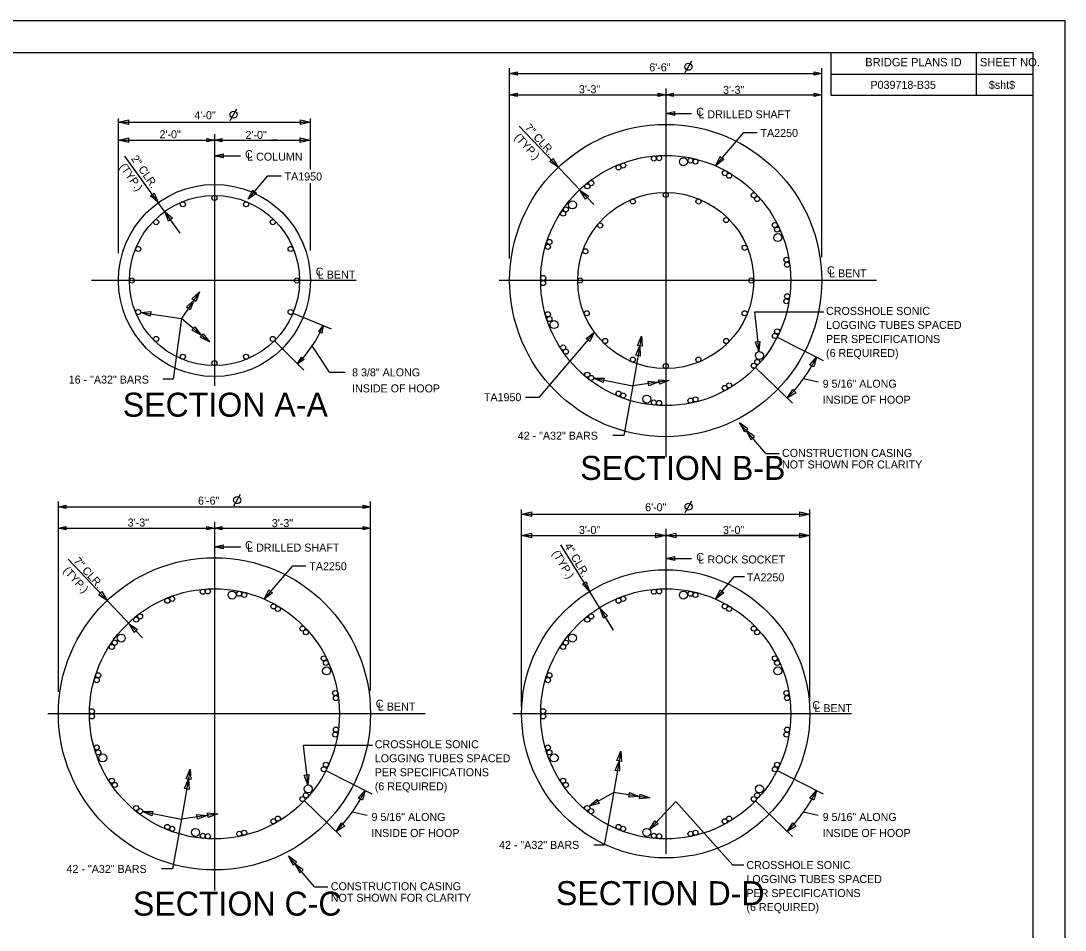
# Model space of a CAD drawing. Extents: x -225.1 to -152.9, y -16.8 to 27.2.
# Drawn here: x -185.7 to -153.08, y -1.16 to 27.22 of the extents above; entities that cross this region are included whole.
import ezdxf

# ---------------------------------------------------------------- set-up
doc = ezdxf.new("R2010")
doc.units = 0
for name, color, linetype in [('BR_AUTO DIMENSION', 7, 'Continuous'), ('BR_BORDER LINES', 7, 'Continuous'), ('BR_CENTER LINES', 7, 'Continuous'), ('BR_CONCRETE', 7, 'Continuous'), ('BR_REBAR', 7, 'Continuous'), ('BR_TEXT', 7, 'Continuous'), ('Level 31', 7, 'Continuous')]:
    doc.layers.add(name, color=color, linetype=linetype)

msp = doc.modelspace()

# ---------------------------------------------------------------- linework, layer by layer
at = {"layer": 'BR_AUTO DIMENSION'}
for p, q in [((-170.43, 19.805), (-170.43, 25.748)), ((-170.43, 25.58), (-160.68, 25.58)), ((-160.68, 19.843), (-160.68, 25.748)), ((-170.43, 24.914), (-165.555, 24.914)), ((-165.555, 24.914), (-160.68, 24.914)), ((-182.652, 19.974), (-182.652, 24.175)), ((-176.652, 22.581), (-176.652, 24.175)), ((-165.555, 24.335), (-164.744, 24.335)), ((-182.652, 24.066), (-176.652, 24.066)), ((-167.801, 21.487), (-170.129, 23.942)), ((-182.652, 23.503), (-176.652, 23.503)), ((-164.001, 22.702), (-163.111, 23.742)), ((-163.111, 23.742), (-162.698, 23.742)), ((-180.722, 20.6), (-182.453, 22.996)), ((-179.652, 23.013), (-178.841, 23.013)), ((-178.6, 21.659), (-177.98, 22.383)), ((-177.98, 22.383), (-177.567, 22.383)), ((-176.652, 20.054), (-176.652, 22.159)), ((-180.118, 18.763), (-180.684, 17.937)), ((-181.954, 18.12), (-180.684, 17.937)), ((-177.198, 18.102), (-176.002, 17.606)), ((-160.615, 18.132), (-162.786, 18.132)), ((-162.786, 18.132), (-162.643, 16.9)), ((-180.684, 17.937), (-180.942, 16.04)), ((-179.809, 17.197), (-180.684, 17.937)), ((-167.78, 17.501), (-169.523, 15.462)), ((-166.312, 17.386), (-166.584, 15.828)), ((-162.072, 17.351), (-160.639, 16.624)), ((-177.774, 17.24), (-176.858, 16.324)), ((-176.061, 16.256), (-176.597, 17.077)), ((-162.748, 16.402), (-161.593, 15.285)), ((-180.942, 16.04), (-181.262, 16.04)), ((-176.061, 16.256), (-175.564, 16.256)), ((-167.8, 16.069), (-166.584, 15.828)), ((-165.451, 15.997), (-166.584, 15.828)), ((-160.789, 15.946), (-161.252, 16.052)), ((-166.584, 15.828), (-166.862, 14.277)), ((-169.523, 15.462), (-169.936, 15.462)), ((-162.427, 13.719), (-163.245, 14.674)), ((-166.862, 14.277), (-167.211, 14.277)), ((-162.427, 13.719), (-162.014, 13.719)), ((-184.527, 6.277), (-184.527, 12.22)), ((-174.777, 6.315), (-174.777, 12.22)), ((-184.527, 12.052), (-174.777, 12.052)), ((-170.055, 5.815), (-170.055, 11.971)), ((-170.055, 11.825), (-161.055, 11.825)), ((-161.055, 5.995), (-161.055, 11.971)), ((-184.527, 11.386), (-179.652, 11.386)), ((-179.652, 11.386), (-174.777, 11.386)), ((-170.055, 11.158), (-165.555, 11.158)), ((-165.555, 11.158), (-161.055, 11.158)), ((-179.652, 10.807), (-178.841, 10.807)), ((-167.182, 8.204), (-168.835, 10.861)), ((-181.898, 7.959), (-184.226, 10.414)), ((-178.097, 9.174), (-177.207, 10.214)), ((-177.207, 10.214), (-176.795, 10.214)), ((-165.555, 10.436), (-164.744, 10.436)), ((-164.001, 9.174), (-163.402, 9.875)), ((-163.402, 9.875), (-163.092, 9.875)), ((-174.712, 4.604), (-176.882, 4.604)), ((-176.882, 4.604), (-176.74, 3.372)), ((-166.958, 4.424), (-167.23, 2.865)), ((-180.408, 3.858), (-180.681, 2.3)), ((-176.168, 3.823), (-174.735, 3.096)), ((-162.072, 3.823), (-160.639, 3.096)), ((-167.947, 2.704), (-167.182, 3.138)), ((-166.05, 2.961), (-167.182, 3.138)), ((-176.844, 2.875), (-175.689, 1.757)), ((-167.23, 2.865), (-167.476, 1.492)), ((-165.234, 2.851), (-166.057, 1.974)), ((-163.454, 0.862), (-165.234, 2.851)), ((-162.748, 2.875), (-161.593, 1.757)), ((-181.896, 2.541), (-180.681, 2.3)), ((-180.681, 2.3), (-180.959, 0.749)), ((-179.547, 2.469), (-180.681, 2.3)), ((-174.885, 2.418), (-175.349, 2.524)), ((-160.789, 2.418), (-161.252, 2.524)), ((-167.476, 1.492), (-167.796, 1.492)), ((-176.524, 0.191), (-177.341, 1.147)), ((-180.959, 0.749), (-181.308, 0.749)), ((-163.113, 0.862), (-163.454, 0.862)), ((-176.524, 0.191), (-176.111, 0.191))]:
    msp.add_line(p, q, dxfattribs=at)
for points in [[(-170.196, 25.526), (-170.43, 25.58), (-170.196, 25.634)], [(-160.914, 25.634), (-160.68, 25.58), (-160.914, 25.526)], [(-170.196, 24.86), (-170.43, 24.914), (-170.196, 24.968)], [(-165.789, 24.968), (-165.555, 24.914), (-165.789, 24.86)], [(-165.321, 24.86), (-165.555, 24.914), (-165.321, 24.968)], [(-160.914, 24.968), (-160.68, 24.914), (-160.914, 24.86)], [(-165.278, 24.271), (-165.555, 24.335), (-165.278, 24.399)], [(-182.34, 23.994), (-182.652, 24.066), (-182.34, 24.138)], [(-176.964, 24.138), (-176.652, 24.066), (-176.964, 23.994)], [(-182.34, 23.431), (-182.652, 23.503), (-182.34, 23.575)], [(-179.886, 23.557), (-179.652, 23.503), (-179.886, 23.449)], [(-179.418, 23.449), (-179.652, 23.503), (-179.418, 23.557)], [(-176.973, 23.573), (-176.661, 23.501), (-176.973, 23.429)], [(-179.375, 22.949), (-179.652, 23.013), (-179.375, 23.077)], [(-169.072, 22.932), (-168.91, 22.656), (-169.177, 22.832)], [(-163.743, 22.892), (-164.001, 22.702), (-163.853, 22.986)], [(-178.342, 21.849), (-178.6, 21.659), (-178.451, 21.943)], [(-168.059, 21.654), (-168.222, 21.93), (-167.955, 21.753)], [(-181.533, 21.845), (-181.409, 21.55), (-181.65, 21.761)], [(-181.083, 20.976), (-181.207, 21.271), (-180.966, 21.061)], [(-180.354, 18.547), (-180.118, 18.764), (-180.235, 18.465)], [(-180.53, 18.289), (-180.295, 18.506), (-180.411, 18.208)], [(-181.656, 18.004), (-181.954, 18.12), (-181.635, 18.147)], [(-180.261, 17.673), (-180.069, 17.417), (-180.354, 17.563)], [(-176.394, 17.515), (-176.257, 17.712), (-176.294, 17.475)], [(-180.003, 17.456), (-179.811, 17.199), (-180.096, 17.346)], [(-168.037, 17.311), (-167.78, 17.501), (-167.928, 17.217)], [(-166.437, 17.091), (-166.312, 17.386), (-166.295, 17.066)], [(-166.49, 16.784), (-166.366, 17.079), (-166.348, 16.759)], [(-162.61, 17.218), (-162.643, 16.9), (-162.753, 17.201)], [(-176.854, 16.654), (-177.054, 16.52), (-176.933, 16.728)], [(-161.056, 16.488), (-160.843, 16.727), (-160.929, 16.419)], [(-167.511, 15.93), (-167.8, 16.069), (-167.48, 16.071)], [(-165.772, 16.022), (-165.453, 15.997), (-165.751, 15.879)], [(-166.106, 15.971), (-165.787, 15.946), (-166.085, 15.829)], [(-161.484, 15.611), (-161.757, 15.444), (-161.584, 15.714)], [(-162.987, 14.484), (-163.245, 14.674), (-163.097, 14.39)], [(-162.784, 14.247), (-163.042, 14.437), (-162.894, 14.153)], [(-184.293, 11.998), (-184.527, 12.052), (-184.293, 12.106)], [(-175.011, 12.106), (-174.777, 12.052), (-175.011, 11.998)], [(-169.743, 11.753), (-170.055, 11.825), (-169.743, 11.897)], [(-161.367, 11.897), (-161.055, 11.825), (-161.367, 11.753)], [(-184.293, 11.332), (-184.527, 11.386), (-184.293, 11.44)], [(-179.886, 11.44), (-179.652, 11.386), (-179.886, 11.332)], [(-179.418, 11.332), (-179.652, 11.386), (-179.418, 11.44)], [(-175.011, 11.44), (-174.777, 11.386), (-175.011, 11.332)], [(-169.743, 11.086), (-170.055, 11.158), (-169.743, 11.23)], [(-165.867, 11.23), (-165.555, 11.158), (-165.867, 11.086)], [(-165.243, 11.086), (-165.555, 11.158), (-165.243, 11.23)], [(-161.367, 11.23), (-161.055, 11.158), (-161.367, 11.086)], [(-179.375, 10.743), (-179.652, 10.807), (-179.375, 10.871)], [(-165.278, 10.372), (-165.555, 10.436), (-165.278, 10.5)], [(-168.037, 9.714), (-167.933, 9.411), (-168.159, 9.638)], [(-183.169, 9.404), (-183.006, 9.128), (-183.273, 9.305)], [(-177.84, 9.364), (-178.097, 9.174), (-177.949, 9.458)], [(-163.744, 9.364), (-164.001, 9.174), (-163.853, 9.458)], [(-167.499, 8.577), (-167.603, 8.88), (-167.377, 8.654)], [(-182.156, 8.126), (-182.318, 8.402), (-182.051, 8.225)], [(-167.082, 4.129), (-166.958, 4.423), (-166.941, 4.104)], [(-167.136, 3.821), (-167.011, 4.116), (-166.994, 3.796)], [(-180.533, 3.563), (-180.408, 3.858), (-180.391, 3.538)], [(-176.707, 3.691), (-176.74, 3.372), (-176.85, 3.673)], [(-180.587, 3.256), (-180.462, 3.551), (-180.445, 3.231)], [(-175.152, 2.96), (-174.94, 3.199), (-175.026, 2.891)], [(-166.684, 3.132), (-166.386, 3.013), (-166.706, 2.99)], [(-166.35, 3.081), (-166.053, 2.962), (-166.372, 2.939)], [(-161.056, 2.96), (-160.843, 3.199), (-160.929, 2.891)], [(-167.638, 2.788), (-167.947, 2.704), (-167.705, 2.915)], [(-181.608, 2.402), (-181.896, 2.541), (-181.576, 2.543)], [(-180.203, 2.443), (-179.884, 2.418), (-180.181, 2.301)], [(-179.869, 2.494), (-179.55, 2.469), (-179.848, 2.352)], [(-175.58, 2.083), (-175.854, 1.917), (-175.681, 2.186)], [(-165.79, 2.152), (-166.057, 1.974), (-165.895, 2.251)], [(-161.484, 2.083), (-161.757, 1.917), (-161.584, 2.186)], [(-177.084, 0.956), (-177.341, 1.147), (-177.193, 0.863)], [(-176.881, 0.719), (-177.138, 0.909), (-176.99, 0.626)]]:
    msp.add_lwpolyline(points, close=True, dxfattribs=at)
for centre in [(-165.003, 22.827), (-168.467, 21.481), (-162.053, 20.458), (-169.043, 17.741), (-162.627, 16.776), (-166.146, 15.415), (-179.099, 9.299), (-165.003, 9.299), (-182.564, 7.954), (-168.467, 7.954), (-176.149, 6.93), (-162.053, 6.93), (-183.14, 4.213), (-169.043, 4.213), (-176.723, 3.248), (-162.627, 3.248), (-180.243, 1.887), (-166.146, 1.887)]:
    msp.add_circle(centre, 0.125, dxfattribs=at)
for centre, radius, start, end in [((-179.652, 19.118), 3.675, 315.0002, 337.5001), ((-165.555, 19.118), 5.284, 315.9545, 333.0973), ((-179.652, 5.59), 5.284, 315.9545, 333.0973), ((-165.555, 5.59), 5.284, 315.9545, 333.0973)]:
    msp.add_arc(centre, radius, start, end, dxfattribs=at)
at = {"layer": 'BR_BORDER LINES'}
for p, q in [((-154.078, 26.224), (-221.411, 26.224)), ((-160.383, 24.89), (-160.383, 26.224)), ((-155.85, 24.89), (-155.85, 26.224)), ((-154.078, -15.776), (-154.078, 26.224)), ((-160.383, 25.565), (-154.078, 25.565)), ((-155.85, 25.565), (-154.078, 25.565)), ((-154.078, 24.89), (-160.383, 24.89))]:
    msp.add_line(p, q, dxfattribs=at)
at = {"layer": 'BR_CENTER LINES'}
for p, q in [((-165.555, 25.113), (-165.555, 13.603)), ((-179.652, 23.691), (-179.652, 15.828)), ((-175.229, 19.118), (-183.493, 19.118)), ((-158.974, 19.118), (-170.758, 19.118)), ((-179.652, 11.585), (-179.652, 0.076)), ((-165.555, 11.367), (-165.555, 1.215)), ((-173.07, 5.59), (-184.855, 5.59)), ((-159.749, 5.59), (-170.327, 5.59))]:
    msp.add_line(p, q, dxfattribs=at)
at = {"layer": 'BR_CONCRETE'}
for centre, radius in [((-165.555, 19.118), 4.875), ((-179.652, 19.118), 3), ((-179.652, 5.59), 4.875), ((-165.555, 5.59), 4.5)]:
    msp.add_circle(centre, radius, dxfattribs=at)
at = {"layer": 'BR_REBAR'}
for centre, radius in [((-165.555, 19.118), 3.906), ((-165.921, 22.928), 0.0794), ((-165.762, 22.939), 0.0794), ((-164.781, 22.866), 0.0794), ((-164.627, 22.831), 0.0794), ((-167.027, 22.651), 0.0794), ((-166.879, 22.709), 0.0794), ((-163.711, 22.471), 0.0794), ((-167.879, 22.159), 0.0794), ((-163.574, 22.392), 0.0794), ((-165.555, 19.118), 2.75), ((-168.003, 22.06), 0.0794), ((-165.555, 21.789), 0.0794), ((-162.805, 21.779), 0.0794), ((-179.652, 19.118), 2.656), ((-180.638, 21.499), 0.0794), ((-179.652, 21.695), 0.0794), ((-178.666, 21.499), 0.0794), ((-166.577, 21.586), 0.0794), ((-164.533, 21.586), 0.0794), ((-162.697, 21.662), 0.0794), ((-168.761, 21.208), 0.0794), ((-168.672, 21.339), 0.0794), ((-181.474, 20.94), 0.0794), ((-177.83, 20.94), 0.0794), ((-167.601, 20.835), 0.0794), ((-163.667, 21.007), 0.0794), ((-162.143, 20.85), 0.0794), ((-162.074, 20.707), 0.0794), ((-169.235, 20.17), 0.0794), ((-169.188, 20.322), 0.0794), ((-182.033, 20.104), 0.0794), ((-177.271, 20.104), 0.0794), ((-168.065, 20.032), 0.0794), ((-163.088, 20.14), 0.0794), ((-161.784, 19.767), 0.0794), ((-161.76, 19.61), 0.0794), ((-169.382, 19.198), 0.0794), ((-182.229, 19.118), 0.0794), ((-177.075, 19.118), 0.0794), ((-169.382, 19.039), 0.0794), ((-168.226, 19.118), 0.0794), ((-162.885, 19.118), 0.0794), ((-161.76, 18.626), 0.0794), ((-161.784, 18.469), 0.0794), ((-182.033, 18.132), 0.0794), ((-177.271, 18.132), 0.0794), ((-169.235, 18.066), 0.0794), ((-169.188, 17.915), 0.0794), ((-168.023, 18.096), 0.0794), ((-163.088, 18.096), 0.0794), ((-181.474, 17.296), 0.0794), ((-177.83, 17.296), 0.0794), ((-167.444, 17.23), 0.0794), ((-163.667, 17.23), 0.0794), ((-162.143, 17.387), 0.0794), ((-162.074, 17.53), 0.0794), ((-168.761, 17.028), 0.0794), ((-168.672, 16.897), 0.0794), ((-180.638, 16.737), 0.0794), ((-178.666, 16.737), 0.0794), ((-166.577, 16.651), 0.0794), ((-164.533, 16.651), 0.0794), ((-162.697, 16.574), 0.0794), ((-179.652, 16.541), 0.0794), ((-165.555, 16.448), 0.0794), ((-162.805, 16.458), 0.0794), ((-168.003, 16.176), 0.0794), ((-167.879, 16.077), 0.0794), ((-167.027, 15.586), 0.0794), ((-163.711, 15.765), 0.0794), ((-163.574, 15.844), 0.0794), ((-166.879, 15.528), 0.0794), ((-165.921, 15.309), 0.0794), ((-165.762, 15.297), 0.0794), ((-164.781, 15.37), 0.0794), ((-164.627, 15.406), 0.0794), ((-179.652, 5.59), 3.906), ((-180.017, 9.4), 0.0794), ((-179.859, 9.412), 0.0794), ((-165.555, 5.59), 3.906), ((-165.921, 9.4), 0.0794), ((-165.762, 9.412), 0.0794), ((-181.124, 9.123), 0.0794), ((-180.976, 9.181), 0.0794), ((-178.878, 9.338), 0.0794), ((-178.723, 9.303), 0.0794), ((-167.027, 9.123), 0.0794), ((-166.879, 9.181), 0.0794), ((-164.781, 9.338), 0.0794), ((-164.627, 9.303), 0.0794), ((-177.808, 8.943), 0.0794), ((-177.67, 8.864), 0.0794), ((-163.711, 8.943), 0.0794), ((-163.574, 8.864), 0.0794), ((-182.099, 8.532), 0.0794), ((-181.975, 8.631), 0.0794), ((-168.003, 8.532), 0.0794), ((-167.879, 8.631), 0.0794), ((-176.901, 8.251), 0.0794), ((-176.793, 8.135), 0.0794), ((-162.805, 8.251), 0.0794), ((-162.697, 8.135), 0.0794), ((-182.768, 7.811), 0.0794), ((-168.672, 7.811), 0.0794), ((-182.858, 7.68), 0.0794), ((-168.761, 7.68), 0.0794), ((-176.239, 7.322), 0.0794), ((-176.17, 7.179), 0.0794), ((-162.143, 7.322), 0.0794), ((-162.074, 7.179), 0.0794), ((-183.285, 6.794), 0.0794), ((-169.188, 6.794), 0.0794), ((-183.331, 6.642), 0.0794), ((-169.235, 6.642), 0.0794), ((-175.88, 6.239), 0.0794), ((-161.784, 6.239), 0.0794), ((-175.857, 6.082), 0.0794), ((-161.76, 6.082), 0.0794), ((-183.478, 5.67), 0.0794), ((-183.478, 5.511), 0.0794), ((-169.382, 5.67), 0.0794), ((-169.382, 5.511), 0.0794), ((-175.88, 4.942), 0.0794), ((-175.857, 5.099), 0.0794), ((-161.784, 4.942), 0.0794), ((-161.76, 5.099), 0.0794), ((-183.331, 4.538), 0.0794), ((-169.235, 4.538), 0.0794), ((-183.285, 4.387), 0.0794), ((-169.188, 4.387), 0.0794), ((-176.239, 3.859), 0.0794), ((-176.17, 4.002), 0.0794), ((-162.143, 3.859), 0.0794), ((-162.074, 4.002), 0.0794), ((-182.858, 3.501), 0.0794), ((-182.768, 3.369), 0.0794), ((-168.761, 3.501), 0.0794), ((-168.672, 3.369), 0.0794), ((-176.901, 2.93), 0.0794), ((-176.793, 3.046), 0.0794), ((-162.805, 2.93), 0.0794), ((-162.697, 3.046), 0.0794), ((-182.099, 2.649), 0.0794), ((-181.975, 2.55), 0.0794), ((-168.003, 2.649), 0.0794), ((-167.879, 2.55), 0.0794), ((-177.808, 2.237), 0.0794), ((-177.67, 2.317), 0.0794), ((-163.711, 2.237), 0.0794), ((-163.574, 2.317), 0.0794), ((-181.124, 2.058), 0.0794), ((-180.976, 2), 0.0794), ((-167.027, 2.058), 0.0794), ((-166.879, 2), 0.0794), ((-180.017, 1.781), 0.0794), ((-179.859, 1.769), 0.0794), ((-178.878, 1.843), 0.0794), ((-178.723, 1.878), 0.0794), ((-165.921, 1.781), 0.0794), ((-165.762, 1.769), 0.0794), ((-164.781, 1.843), 0.0794), ((-164.627, 1.878), 0.0794)]:
    msp.add_circle(centre, radius, dxfattribs=at)
at = {"layer": 'BR_TEXT'}
for p, q in [((-164.95, 25.609), (-164.74, 25.973)), ((-179.16, 24.116), (-178.95, 24.479)), ((-182.277, 23.503), (-182.111, 23.503)), ((-179.652, 23.503), (-179.823, 23.503)), ((-179.652, 23.503), (-179.468, 23.503)), ((-177.683, 23.503), (-177.86, 23.503)), ((-179.047, 12.082), (-178.837, 12.445)), ((-164.947, 11.875), (-164.737, 12.238)), ((-170.055, 11.158), (-169.834, 11.158)), ((-165.555, 11.158), (-165.783, 11.158)), ((-165.555, 11.158), (-165.311, 11.158)), ((-161.055, 11.158), (-163.763, 11.158))]:
    msp.add_line(p, q, dxfattribs=at)
for centre in [(-164.845, 25.791), (-179.055, 24.298), (-178.942, 12.263), (-164.842, 12.057)]:
    msp.add_circle(centre, 0.11, dxfattribs=at)
at = {"layer": 'Level 31'}
msp.add_lwpolyline([(-225.077, -16.776), (-153.077, -16.776), (-153.077, 27.224), (-225.077, 27.224)], close=True, dxfattribs=at)

# ---------------------------------------------------------------- texts
at = {"layer": 'BR_TEXT'}
for s, height, rotation, p in [('6\'-6" ', 0.25, 360, (-166.069, 25.649)), ('3\'-3"', 0.25, 360, (-168.266, 24.965)), ('3\'-3"', 0.25, 360, (-163.764, 24.946)), ('4\'-0" ', 0.25, 360, (-180.279, 24.155)), ('L DRILLED SHAFT', 0.24999, 360, (-164.532, 24.183)), ('7" CLR.', 0.25, 312.3922, (-169.977, 23.871)), ('TA2250', 0.25, 360, (-162.593, 23.6)), ('2\'-0"', 0.25, 360, (-181.37, 23.557)), ('2\'-0"', 0.25, 360, (-178.683, 23.538)), ('(TYP.)', 0.25, 312.3922, (-170.3, 23.576)), ('2" CLR.', 0.25, 304.7565, (-182.271, 22.924)), ('L COLUMN', 0.25, 360, (-178.629, 22.86)), ('(TYP.)', 0.25, 304.7565, (-182.63, 22.674)), ('TA1950', 0.25, 360, (-177.462, 22.241)), ('L BENT', 0.25, 360, (-176.422, 19.178)), ('L BENT', 0.25, 360, (-160.45, 19.218)), ('L BENT', 0.25, 360, (-160.45, 19.218)), ('CROSSHOLE SONIC', 0.24999, 360, (-160.546, 18.043)), ('LOGGING TUBES SPACED', 0.24999, 360, (-160.546, 17.605)), ('PER SPECIFICATIONS', 0.24999, 360, (-160.546, 17.168)), ('(6 REQUIRED)', 0.24999, 360, (-160.546, 16.73)), ('8 3/8" ALONG', 0.24999, 360, (-175.353, 16.125)), ('16 - "A32" BARS', 0.24999, 360, (-184.205, 15.901)), ('9 5/16" ALONG', 0.24999, 360, (-160.65, 15.772)), ('INSIDE OF HOOP', 0.24999, 360, (-175.353, 15.625)), ('TA1950', 0.25, 360, (-171.235, 15.35)), ('INSIDE OF HOOP', 0.24999, 360, (-160.65, 15.272)), ('42 - "A32" BARS', 0.24999, 360, (-170.178, 14.149)), ('CONSTRUCTION CASING', 0.24999, 360, (-161.922, 13.61)), ('NOT SHOWN FOR CLARITY', 0.24999, 360, (-161.922, 13.25)), ('6\'-6" ', 0.25, 360, (-180.166, 12.121)), ('6\'-0"', 0.25, 360, (-166.198, 11.914)), ('3\'-3"', 0.25, 360, (-182.362, 11.437)), ('3\'-3"', 0.25, 360, (-177.861, 11.418)), ('3\'-0"', 0.25, 360, (-168.267, 11.207)), ('3\'-0"', 0.25, 360, (-163.767, 11.207)), ('L DRILLED SHAFT', 0.24999, 360, (-178.629, 10.655)), ('4" CLR.', 0.25, 300.8062, (-168.733, 10.834)), ('7" CLR.', 0.25, 312.3922, (-184.074, 10.343)), ('(TYP.)', 0.25, 300.8062, (-169.109, 10.609)), ('L ROCK SOCKET', 0.24999, 360, (-164.532, 10.284)), ('(TYP.)', 0.25, 312.3922, (-184.397, 10.048)), ('TA2250', 0.25, 360, (-176.689, 10.073)), ('TA2250', 0.25, 360, (-163.02, 9.724)), ('L BENT', 0.25, 360, (-174.547, 5.69)), ('L BENT', 0.25, 360, (-174.547, 5.69)), ('L BENT', 0.25, 360, (-160.908, 5.643)), ('CROSSHOLE SONIC', 0.24999, 360, (-174.643, 4.515)), ('LOGGING TUBES SPACED', 0.24999, 360, (-174.643, 4.077)), ('PER SPECIFICATIONS', 0.24999, 360, (-174.643, 3.64)), ('(6 REQUIRED)', 0.24999, 360, (-174.643, 3.202)), ('9 5/16" ALONG', 0.24999, 360, (-174.746, 2.245)), ('9 5/16" ALONG', 0.24999, 360, (-160.65, 2.245)), ('INSIDE OF HOOP', 0.24999, 360, (-174.746, 1.745)), ('INSIDE OF HOOP', 0.24999, 360, (-160.65, 1.745)), ('42 - "A32" BARS', 0.24999, 360, (-170.761, 1.372)), ('CROSSHOLE SONIC', 0.24999, 360, (-163.033, 0.743)), ('42 - "A32" BARS', 0.24999, 360, (-184.274, 0.622)), ('CONSTRUCTION CASING', 0.24999, 360, (-176.018, 0.082)), ('LOGGING TUBES SPACED', 0.24999, 360, (-163.033, 0.306)), ('PER SPECIFICATIONS', 0.24999, 360, (-163.033, -0.132)), ('NOT SHOWN FOR CLARITY', 0.24999, 360, (-176.018, -0.278)), ('(6 REQUIRED)', 0.24999, 360, (-163.033, -0.569))]:
    msp.add_text(s, height=height, rotation=rotation, dxfattribs=at).set_placement(p)
for s, height, p in [('BRIDGE PLANS ID', 0.26, (-159.321, 25.805)), ('SHEET NO.', 0.26, (-155.739, 25.805)), ('P039718-B35', 0.25, (-159.158, 25.102)), ('$sht$', 0.25, (-155.459, 25.102)), ('C', 0.25, (-164.6, 24.26)), ('C', 0.25, (-178.697, 22.938)), ('C', 0.25, (-176.488, 19.27)), ('C', 0.25, (-160.517, 19.31)), ('C', 0.25, (-160.517, 19.31)), ('SECTION A-A', 0.74998, (-182.517, 14.866)), ('SECTION B-B', 0.74998, (-168.224, 12.893)), ('C', 0.25, (-178.697, 10.732)), ('C', 0.25, (-164.6, 10.362)), ('C', 0.25, (-174.613, 5.782)), ('C', 0.25, (-174.613, 5.782)), ('C', 0.25, (-160.975, 5.735)), ('SECTION D-D', 0.74998, (-168.984, -0.384)), ('SECTION C-C', 0.74998, (-182.2, -0.712))]:
    msp.add_text(s, height=height, dxfattribs=at).set_placement(p)

doc.saveas('drawing.dxf')
